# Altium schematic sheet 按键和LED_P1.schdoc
size 297 x 209 mm; Symbol: Drawing-Symbol_A4; Company: 嘉立创EDA; Version: V1.0; Page Size: A4; @Project Name: 水墨屏demo1; @Page Count: 1; @Update Date: 2026-02-28; @Create Date: 2026-02-28; @Schematic Name: Schematic1; @Page No: 1; @Page Name: P1; Device: Drawing-Symbol_A4; @Board Name: Board1; @Create Time: 16:54:16; @Update Time: 16:54:16; @Assembly Variant: Basic; Border: 1; Title Block Position: 3; Size: A4; Width: 1170; Height: 825; Region Start: 1; X Region Count: 6; Y Region Count: 4; Blade Width: 10
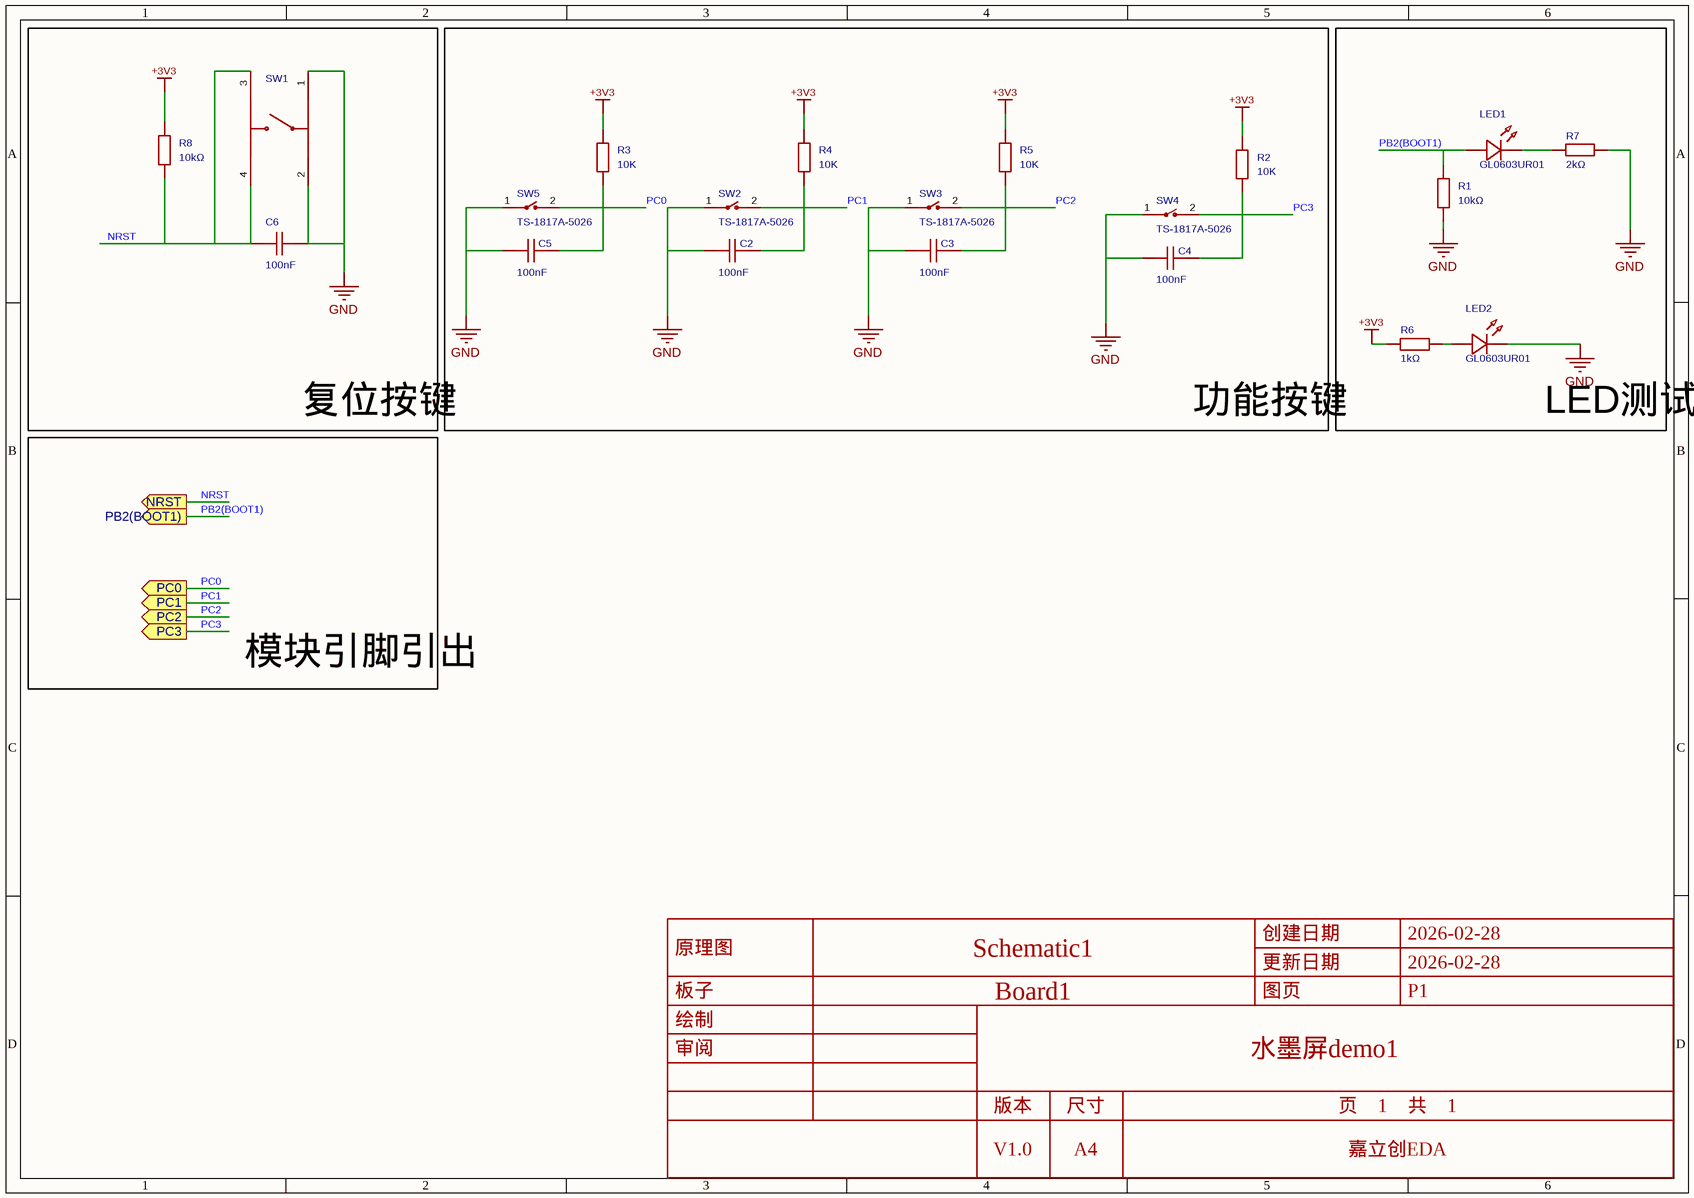
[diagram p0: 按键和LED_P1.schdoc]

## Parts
C2  100nF  [C0603]
C3  100nF  [C0603]
C4  100nF  [C0603]
C5  100nF  [C0603]
C6  100nF  [C0603]
LED1  GL0603UR01  [LED0603-FD]
LED2  GL0603UR01  [LED0603-FD]
R1  10kΩ  [R0603]
R2  10K  [R0603]
R3  10K  [R0603]
R4  10K  [R0603]
R5  10K  [R0603]
R6  1kΩ  [R0603]
R7  2kΩ  [R0603]
R8  10kΩ  [R0603]
SW1  TSA017A2540A03  [SW-SMD_4P-L4.2-W3.4-P2.15-LS5.2]  (value not drawn)
SW2  TS-1817A-5026  [SW-SMD_L6.0-W6.0-LS8.0]
SW3  TS-1817A-5026  [SW-SMD_L6.0-W6.0-LS8.0]
SW4  TS-1817A-5026  [SW-SMD_L6.0-W6.0-LS8.0]
SW5  TS-1817A-5026  [SW-SMD_L6.0-W6.0-LS8.0]

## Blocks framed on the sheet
复位按键: C6 R8 SW1
功能按键: C2-C5 R2-R5 SW2-SW5
LED测试: LED1 LED2 R1 R6 R7

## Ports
NRST (out), PB2(BOOT1) (out), PC0 (out), PC1 (out), PC2 (out), PC3 (out)

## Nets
+3V3: R2.2 R3.2 R4.2 R5.2 R6.1 R8.2
GND: C2.1 C3.1 C4.1 C5.1 C6.2 LED2.2(C) R1.1 R7.2 SW1.1 SW1.2 SW2.1 SW3.1 SW4.1 SW5.1
NRST: C6.1 R8.1 SW1.3 SW1.4 ; port NRST
PB2(BOOT1): LED1.1(A) R1.2 ; port PB2(BOOT1)
PC0: C5.2 R3.1 SW5.2 ; port PC0
PC1: C2.2 R4.1 SW2.2 ; port PC1
PC2: C3.2 R5.1 SW3.2 ; port PC2
PC3: C4.2 R2.1 SW4.2 ; port PC3
NetLED1_2: LED1.2(C) R7.1
NetLED2_1: LED2.1(A) R6.2

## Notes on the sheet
- 模块引脚引出

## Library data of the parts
C2-C5 = CAP_0603: Symbol: Capacitance; 3D Model: ac125912035d415993ca9572d50418b1; 3D Model Transform: 62.992,31.496,0,0,0,0,0,0,0; ConvertToPcb: yes; ModelName: C0603_L1.6-W0.8-H0.8
C6 = CGA0603X7R104K500JT: 容值:100nF;精度:±10%;额定电压:50V;温度系数:X7R;; Manufacturer: HRE(芯声); 3D Model: ac125912035d415993ca9572d50418b1; 3D Model Transform: 62.992,31.496,0,0,0,0,0,0,0; Tolerance: ±10%; Voltage Rating: 50V; Temperature Coefficient: X7R; AddInBom: yes; ModelName: C0603_L1.6-W0.8-H0.8
LED1 LED2 = GL0603UR01: 发光颜色:红色;正向压降(Vf):2.4V;正向电流:20mA;波长:620nm~625nm;二极管配置:独立二极管;透镜颜色:无色透明透镜;发光强度:120mcd;发光角度:120°;载带方式:正贴;工作温度:-40℃~+85℃;; Manufacturer: Guiguang light(桂光光电); 3D Model: b57d6965da4c4e30afc1a994a1f136ae0819f05c4eef4c71ace90d822a990e87; 3D Model Transform: 60,30,0,0,0,0,0,0,0; Illumination Color: 红色; Voltage - Forward(Vf): 2.4V; Forward Current: 20mA; Diode Configuration: 独立二极管; Lens Color: 无色透明透镜; Luminous Intensity: 120mcd; Viewing Angle: 120°; AddInBom: yes; ModelName: LED0603_Inf
R1 R8 = RC0603FR-0710KL: 电阻类型:厚膜电阻;阻值:10kΩ;精度:±1%;功率:100mW;最大工作电压:75V;温度系数:±100ppm/℃;; Manufacturer: YAGEO(国巨); 3D Model: fc143cca1e79419f9cd78b61e9279f080819f05c4eef4c71ace90d822a990e87; 3D Model Transform: 31.8897,63.7794,0,90,0,0,0,0,0; Tolerance: ±1%; Power(Watts): 100mW; Overload Voltage (Max): 75V; AddInBom: yes
R2-R5 = Res_0603: Symbol: 电阻; 3D Model: fc143cca1e79419f9cd78b61e9279f08; 3D Model Transform: 31.8897,63.7794,0,90,0,0,0,0,0; ConvertToPcb: yes
R6 = RC0603FR-072KL: 电阻类型:厚膜电阻;阻值:2kΩ;精度:±1%;功率:100mW;工作电压:75V;温度系数:±100ppm/℃;; Manufacturer: YAGEO(国巨); 3D Model: fc143cca1e79419f9cd78b61e9279f080819f05c4eef4c71ace90d822a990e87; 3D Model Transform: 31.8897,63.7794,0,90,0,0,0,0,0; Tolerance: ±1%; Power(Watts): 100mW; Voltage-Supply(Max): 75V; AddInBom: yes
R7 = RC0603FR-072KL: 电阻类型:厚膜电阻;阻值:2kΩ;精度:±1%;功率:100mW;工作电压:75V;温度系数:±100ppm/℃;; Manufacturer: YAGEO(国巨); AddInBom: yes; ModelId: fc143cca1e79419f9cd78b61e9279f080819f05c4eef4c71ace90d822a990e87; ModelTransform: 31.8897,63.7794,0,90,0,0,0,0,0; Tolerance: ±1%; Power(Watts): 100mW; Voltage-Supply(Max): 75V
SW1 = TSA017A2540A03: 触点电流:50mA;额定电压(AC):-;额定电压(DC):12V;安装方式:立贴;机械寿命:-;; Manufacturer: BZCN(博众电气); 3D Model: 8f5161de2aba47ef91b81c2f817ddd4f; 3D Model Transform: 204.724,133.858,0,0,0,0,0.002,0.002,0; Contact Current: 50mA; Voltage Rating (DC): 12V; Actuator Style: 椭圆形按钮; Switch Length: 4.2mm; Switch Width: 3.35mm; Switch Height: 2.5mm; AddInBom: yes; ModelName: SW-SMD_4P-L4.2-W3.4-H2.5-P2.15-LS5.2
SW2-SW5 = TS-1817A-5026: 电路结构:单刀单掷;按钮形状:圆形按钮;作用力:2.6N;安装方式:立贴;开关长度:6mm;开关宽度:6mm;开关高度:5mm;触点电流:250mA;额定电压:24V;带灯:-;工作寿命:10万次;; Manufacturer: SOFNG(硕方); 3D Model: 5de9500db0ed4ecc83a18e947e6a0012; 3D Model Transform: 314.96,236.22,0,0,0,0,0,0,0; Circuit: 单刀单掷; Actuator Style: 圆形按钮; Operating Force: 2.6N; Switch Height: 5mm; Contact Current: 250mA; Voltage Rating: 24V; Actuator/Cap Color: 黑色; Life: 10万次; AddInBom: yes; ModelName: SW-SMD_L6.0-W6.0-H5.0-P6.00-LS8.0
